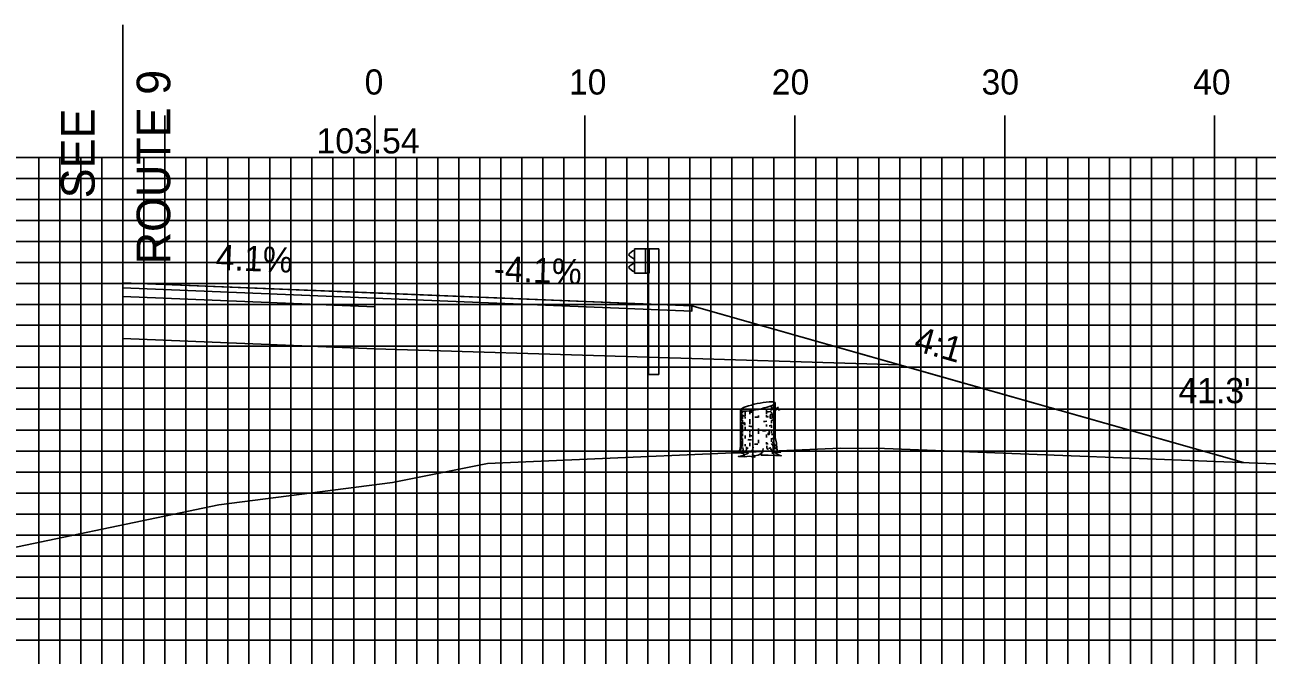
# Model space of a CAD drawing. Extents: x 852542 to 852886, y 364366 to 364586.
# Drawn here: x 852691.5 to 852750.7, y 364395.1 to 364425.1 of the extents above; entities that cross this region are included whole.
import ezdxf

# ---------------------------------------------------------------- set-up
doc = ezdxf.new("R2010")
doc.units = 0
for name, color, linetype in [('ANNOTATION', 7, 'Continuous'), ('D_Guardrail_Beam_Rt', 7, 'Continuous'), ('D_Roadway_Centerline_Text', 7, 'Continuous'), ('D_Roadway_Edge_Shoulder', 7, 'Continuous'), ('D_Roadway_Edge_TW', 7, 'Continuous'), ('D_Roadway_Pavement', 7, 'Continuous'), ('D_Roadway_SlopeLines', 7, 'Continuous'), ('D_Roadway_SubGrade', 7, 'Continuous'), ('D_Text_Standard', 7, 'Continuous'), ('H_V ANNOTATION', 7, 'Continuous'), ('M_Trees_Conifer_Pay', 7, 'Continuous'), ('MAJOR', 7, 'Continuous'), ('MINOR', 7, 'Continuous'), ('S_Roadway_Centerline', 7, 'Continuous')]:
    doc.layers.add(name, color=color, linetype=linetype)

msp = doc.modelspace()

# ---------------------------------------------------------------- linework, layer by layer
at = {"layer": 'D_Guardrail_Beam_Rt'}
for p, q in [((852720.466, 364414.331), (852720.322, 364414.231)), ((852720.322, 364414.088), (852720.518, 364413.952)), ((852720.556, 364414.352), (852720.482, 364414.338)), ((852720.556, 364414.436), (852721.243, 364414.436)), ((852720.556, 364413.269), (852720.556, 364414.436)), ((852721.077, 364414.436), (852721.077, 364413.269)), ((852721.181, 364414.436), (852721.181, 364413.269)), ((852721.243, 364414.436), (852721.714, 364414.436)), ((852721.243, 364414.436), (852721.243, 364413.269)), ((852721.714, 364414.436), (852721.714, 364408.436)), ((852720.518, 364413.753), (852720.322, 364413.617)), ((852720.322, 364413.474), (852720.466, 364413.374)), ((852720.551, 364413.888), (852720.551, 364413.817)), ((852720.482, 364413.367), (852720.556, 364413.352)), ((852721.243, 364413.269), (852720.556, 364413.269)), ((852721.222, 364408.436), (852721.222, 364413.269)), ((852721.222, 364408.436), (852721.714, 364408.436))]:
    msp.add_line(p, q, dxfattribs=at)
for centre, major_axis, start_param, end_param in [((852720.373, 364414.16), (-0.0877, 0), 5.323254, 7.243116), ((852720.49, 364414.297), (-0.0417, 0), 4.907132, 5.323254), ((852720.373, 364413.545), (-0.0877, 0), 5.323254, 7.243116), ((852720.472, 364413.888), (0.0789, 0), 0, 0.959931), ((852720.472, 364413.817), (0.0789, 0), 5.323254, 6.283185), ((852720.49, 364413.408), (-0.0417, 0), 0.959931, 1.376053)]:
    msp.add_ellipse(centre, major_axis=major_axis, ratio=0.995501, start_param=start_param, end_param=end_param, dxfattribs=at)
at = {"layer": 'D_Roadway_Edge_Shoulder'}
for points in [[(852696.178, 364412.82), (852723.285, 364411.714), (852723.285, 364411.464), (852696.178, 364412.57)], [(852696.178, 364412.82), (852723.285, 364411.714), (852723.285, 364411.464), (852696.178, 364412.57)], [(852696.178, 364412.82), (852723.285, 364411.714), (852723.285, 364411.464), (852696.178, 364412.57)], [(852696.178, 364412.82), (852723.285, 364411.714), (852723.285, 364411.464), (852696.178, 364412.57)], [(852696.178, 364412.82), (852723.285, 364411.714), (852723.285, 364411.464), (852696.178, 364412.57)], [(852708.178, 364412.331), (852723.285, 364411.714), (852723.285, 364411.464), (852708.178, 364412.081)], [(852708.178, 364412.331), (852723.285, 364411.714), (852723.285, 364411.464), (852708.178, 364412.081)], [(852708.178, 364412.331), (852723.285, 364411.714), (852723.285, 364411.464), (852708.178, 364412.081)]]:
    msp.add_lwpolyline(points, close=True, dxfattribs=at)
at = {"layer": 'D_Roadway_Edge_TW'}
msp.add_lwpolyline([(852696.178, 364412.82), (852696.178, 364412.57)], dxfattribs=at)
msp.add_lwpolyline([(852696.178, 364412.82), (852696.178, 364412.57)], dxfattribs=at)
msp.add_lwpolyline([(852696.178, 364412.82), (852708.178, 364412.331), (852708.178, 364412.081), (852696.178, 364412.57)], close=True, dxfattribs=at)
msp.add_lwpolyline([(852696.178, 364412.82), (852708.178, 364412.331), (852708.178, 364412.081), (852696.178, 364412.57)], close=True, dxfattribs=at)
msp.add_lwpolyline([(852696.178, 364412.82), (852708.178, 364412.331), (852708.178, 364412.081), (852696.178, 364412.57)], close=True, dxfattribs=at)
at = {"layer": 'D_Roadway_Pavement'}
for points in [[(852696.178, 364412.57), (852696.178, 364412.154)], [(852696.178, 364412.57), (852696.178, 364412.154)], [(852696.178, 364412.57), (852696.178, 364412.154)], [(852696.178, 364412.57), (852696.178, 364412.154)], [(852708.178, 364412.081), (852708.178, 364411.664)], [(852708.178, 364412.081), (852708.178, 364411.664)], [(852708.178, 364412.081), (852708.178, 364411.664)], [(852708.178, 364412.081), (852708.178, 364411.664)], [(852708.178, 364412.081), (852708.178, 364411.664)], [(852708.178, 364412.081), (852708.178, 364411.664)], [(852708.178, 364412.081), (852708.178, 364411.664)], [(852708.178, 364412.081), (852708.178, 364411.664)], [(852708.178, 364412.081), (852708.178, 364411.664)], [(852708.178, 364412.081), (852708.178, 364411.664)], [(852708.178, 364412.081), (852708.178, 364411.664)], [(852708.178, 364412.081), (852708.178, 364411.664)], [(852708.178, 364412.081), (852708.178, 364411.664)], [(852708.178, 364412.081), (852708.178, 364411.664)]]:
    msp.add_lwpolyline(points, dxfattribs=at)
msp.add_lwpolyline([(852696.178, 364412.57), (852708.178, 364412.081), (852708.178, 364411.664), (852696.178, 364412.154)], close=True, dxfattribs=at)
msp.add_lwpolyline([(852696.178, 364412.57), (852708.178, 364412.081), (852708.178, 364411.664), (852696.178, 364412.154)], close=True, dxfattribs=at)
msp.add_lwpolyline([(852696.178, 364412.57), (852708.178, 364412.081), (852708.178, 364411.664), (852696.178, 364412.154)], close=True, dxfattribs=at)
at = {"layer": 'D_Roadway_SlopeLines'}
for points in [[(852723.285, 364411.714), (852735.285, 364408.301), (852749.548, 364404.244)], [(852723.285, 364411.714), (852735.285, 364408.301), (852749.548, 364404.244)], [(852723.285, 364411.714), (852735.285, 364408.301), (852749.548, 364404.244)], [(852723.285, 364411.714), (852735.285, 364408.301), (852749.548, 364404.244)], [(852723.285, 364411.714), (852749.548, 364404.244)]]:
    msp.add_lwpolyline(points, dxfattribs=at)
at = {"layer": 'D_Roadway_SubGrade'}
msp.add_line((852696.178, 364425.111), (852696.178, 364410.154), dxfattribs=at)
for points in [[(852696.178, 364412.154), (852708.178, 364411.664), (852708.178, 364409.664), (852696.178, 364410.154)], [(852696.178, 364412.154), (852708.178, 364411.664), (852708.178, 364409.664), (852696.178, 364410.154)], [(852696.178, 364412.154), (852708.178, 364411.664), (852708.178, 364409.664), (852696.178, 364410.154)], [(852708.178, 364411.664), (852708.178, 364412.081), (852723.285, 364411.464), (852723.285, 364411.714), (852733.164, 364408.905), (852708.178, 364409.664)], [(852708.178, 364411.664), (852708.178, 364412.081), (852723.285, 364411.464), (852723.285, 364411.714), (852733.164, 364408.905), (852708.178, 364409.664)], [(852708.178, 364411.664), (852708.178, 364412.081), (852723.285, 364411.464), (852723.285, 364411.714), (852733.164, 364408.905), (852708.178, 364409.664)], [(852708.178, 364411.664), (852708.178, 364412.081), (852723.285, 364411.464), (852723.285, 364411.714), (852733.164, 364408.905), (852708.178, 364409.664)]]:
    msp.add_lwpolyline(points, close=True, dxfattribs=at)
msp.add_lwpolyline([(852696.178, 364412.154), (852696.178, 364410.154)], dxfattribs=at)
msp.add_lwpolyline([(852696.178, 364412.154), (852696.178, 364410.154)], dxfattribs=at)
at = {"layer": 'M_Trees_Conifer_Pay'}
for p, q in [((852727.065, 364406.952), (852727.065, 364406.729)), ((852727.182, 364407.013), (852727.182, 364406.85)), ((852727.254, 364405.438), (852727.254, 364407.085)), ((852725.589, 364405.028), (852725.589, 364406.75)), ((852725.637, 364406.713), (852725.637, 364406.242)), ((852725.695, 364406.701), (852725.695, 364406.604)), ((852725.695, 364406.53), (852725.695, 364406.325)), ((852725.82, 364406.694), (852725.82, 364406.461)), ((852725.82, 364406.421), (852725.82, 364406.346)), ((852726.04, 364406.714), (852726.04, 364406.546)), ((852726.04, 364406.309), (852726.04, 364406.072)), ((852726.446, 364406.482), (852726.446, 364406.387)), ((852726.836, 364406.756), (852726.836, 364406.556)), ((852726.836, 364406.499), (852726.836, 364406.41)), ((852727.065, 364406.64), (852727.065, 364406.593)), ((852727.122, 364406.457), (852727.07, 364406.398)), ((852727.182, 364406.783), (852727.182, 364406.655)), ((852727.182, 364406.468), (852727.182, 364406.132)), ((852725.637, 364406.177), (852725.637, 364405.869)), ((852725.637, 364405.822), (852725.637, 364405.329)), ((852725.695, 364406.268), (852725.695, 364406.068)), ((852725.695, 364406.021), (852725.695, 364405.685)), ((852725.82, 364405.943), (852725.82, 364405.805)), ((852726.04, 364405.827), (852726.04, 364405.675)), ((852726.446, 364405.869), (852726.446, 364405.795)), ((852726.446, 364405.77), (852726.446, 364405.621)), ((852726.836, 364406.062), (852726.836, 364405.957)), ((852727.065, 364406.258), (852727.065, 364406.126)), ((852727.065, 364406.015), (852727.065, 364405.906)), ((852727.065, 364405.77), (852727.065, 364405.628)), ((852727.182, 364406.095), (852727.182, 364405.932)), ((852727.182, 364405.885), (852727.182, 364405.669)), ((852725.637, 364405.276), (852725.637, 364405.028)), ((852725.695, 364405.632), (852725.695, 364405.496)), ((852725.695, 364405.397), (852725.695, 364405.018)), ((852725.82, 364405.533), (852725.82, 364405.391)), ((852725.82, 364405.129), (852725.82, 364405.035)), ((852726.04, 364405.632), (852726.04, 364405.459)), ((852726.04, 364405.181), (852726.04, 364405.028)), ((852726.446, 364405.329), (852726.446, 364405.177)), ((852726.836, 364405.591), (852726.836, 364405.444)), ((852726.836, 364405.212), (852726.836, 364405.123)), ((852727.065, 364405.401), (852727.065, 364405.228)), ((852727.182, 364405.638), (852727.182, 364405.564)), ((852727.182, 364405.523), (852727.182, 364405.35)), ((852725.82, 364404.635), (852725.983, 364404.699)), ((852726.257, 364404.571), (852726.131, 364404.635))]:
    msp.add_line(p, q, dxfattribs=at)
for points in [[(852727.07, 364406.583), (852727.107, 364406.509), (852727.154, 364406.566), (852727.212, 364406.635), (852727.305, 364406.828), (852727.369, 364406.875), (852727.4, 364406.882)], [(852727.037, 364406.546), (852727.006, 364406.461), (852727.002, 364406.394), (852727.033, 364406.33)], [(852727.085, 364406.33), (852727.122, 364406.457), (852727.185, 364406.573), (852727.216, 364406.64), (852727.285, 364406.787)], [(852727.299, 364406.816), (852727.375, 364406.824), (852727.447, 364406.725)], [(852725.769, 364406.056), (852725.763, 364406.151), (852725.806, 364406.128), (852725.806, 364406.034)], [(852726.908, 364405.657), (852726.92, 364405.58), (852726.967, 364405.591), (852726.955, 364405.757)], [(852727.254, 364405.438), (852727.305, 364405.177), (852727.321, 364404.903), (852727.379, 364404.778), (852727.515, 364404.747), (852727.284, 364404.709), (852727.284, 364404.709), (852727.29, 364404.662), (852727.538, 364404.568), (852727.263, 364404.584), (852726.908, 364404.604), (852726.586, 364404.594), (852726.593, 364404.677), (852726.444, 364404.594), (852726.257, 364404.571), (852726.282, 364404.503), (852726.014, 364404.547), (852725.794, 364404.52), (852725.501, 364404.537), (852725.79, 364404.594), (852725.82, 364404.635), (852725.658, 364404.693), (852725.421, 364404.703), (852725.18, 364404.703), (852725.522, 364404.761), (852725.563, 364404.841), (852725.589, 364405.028)], [(852727.08, 364405.15), (852727.154, 364405.045), (852727.159, 364404.872), (852727.284, 364404.709)], [(852727.179, 364405.296), (852727.185, 364405.15), (852727.233, 364405.082), (852727.243, 364404.883)], [(852725.637, 364404.981), (852725.616, 364404.903), (852725.596, 364404.808)], [(852725.715, 364404.961), (852725.721, 364404.845), (852725.668, 364404.757), (852725.658, 364404.693)], [(852725.878, 364404.988), (852725.878, 364404.856), (852725.79, 364404.757)], [(852726.105, 364404.747), (852726.172, 364404.841), (852726.199, 364404.981)], [(852726.593, 364404.677), (852726.667, 364404.818), (852726.677, 364404.919)], [(852726.843, 364405.045), (852726.854, 364404.919), (852726.928, 364404.876)], [(852727.122, 364404.656), (852727.107, 364404.794), (852727.033, 364404.923)]]:
    msp.add_lwpolyline(points, dxfattribs=at)
for centre, radius, start, end in [((852726.088, 364406.144), 0.802, 108.05939, 124.2194), ((852727.445, 364401.983), 5.179, 101.7194, 108.05939), ((852727.445, 364401.983), 5.179, 95.37941, 101.7194), ((852725.398, 364411.853), 5.179, 281.7194, 288.05939), ((852727.035, 364406.34), 0.802, 79.2194, 95.37941), ((852726.755, 364407.691), 0.802, 288.05939, 304.2194), ((852727.138, 364406.882), 0.251, 71.05013, 79.2194), ((852727.065, 364407.236), 0.251, 304.2194, 312.38868), ((852727.122, 364407.054), 0.172, 300, 311.25059), ((852727.193, 364407.041), 0.0817, 56.7194, 71.05013), ((852727.179, 364407.111), 0.0817, 312.38868, 326.7194), ((852727.194, 364406.971), 0.0624, 311.25059, 330), ((852727.209, 364407.066), 0.0527, 46.92298, 56.7194), ((852727.223, 364407.081), 0.0314, 34.2194, 46.92298), ((852727.203, 364407.095), 0.0527, 326.7194, 336.51582), ((852727.21, 364406.962), 0.0441, 330, 343.94846), ((852727.227, 364407.084), 0.0264, 23.40735, 34.2194), ((852727.222, 364407.086), 0.0314, 336.51582, 349.2194), ((852727.231, 364407.086), 0.0226, 11.7194, 23.40735), ((852727.22, 364406.959), 0.0334, 343.94846, 354.21506), ((852727.231, 364407.086), 0.0226, 0.03145, 11.7194), ((852727.227, 364407.086), 0.0264, 349.2194, 0.03145), ((852725.622, 364406.572), 0.0334, 163.94846, 180), ((852725.622, 364406.572), 0.0334, 180, 196.05154), ((852725.621, 364406.749), 0.0314, 156.51582, 169.2194), ((852725.616, 364406.75), 0.0264, 169.2194, 180.03145), ((852725.612, 364406.75), 0.0226, 180.03145, 191.7194), ((852725.612, 364406.75), 0.0226, 191.7194, 203.40735), ((852725.632, 364406.575), 0.0441, 196.05154, 210), ((852725.616, 364406.751), 0.0264, 203.40735, 214.2194), ((852725.64, 364406.74), 0.0527, 146.7194, 156.51582), ((852725.62, 364406.754), 0.0314, 214.2194, 226.92298), ((852725.648, 364406.584), 0.0624, 210, 228.74941), ((852725.665, 364406.724), 0.0817, 132.38868, 146.7194), ((852725.634, 364406.77), 0.0527, 226.92298, 236.7194), ((852725.65, 364406.794), 0.0817, 236.7194, 251.05013), ((852725.72, 364406.666), 0.172, 228.74941, 240), ((852725.779, 364406.6), 0.251, 124.2194, 132.38868), ((852725.705, 364406.954), 0.251, 251.05013, 259.2194), ((852725.919, 364407.012), 0.571, 240, 240.33672), ((852725.921, 364406.8), 0.571, 240, 247.05866), ((852725.808, 364407.495), 0.802, 259.2194, 275.37941), ((852725.919, 364407.012), 0.571, 246.85973, 257.98457), ((852725.398, 364411.853), 5.179, 275.37941, 281.7194), ((852726.422, 364410.762), 4.124, 264.6955, 266.73309), ((852726.42, 364410.529), 4.124, 268.07512, 270), ((852726.42, 364410.529), 4.124, 270, 270.35814), ((852726.42, 364410.529), 4.124, 275.78493, 277.05584), ((852726.422, 364410.762), 4.124, 276.23804, 278.1032), ((852726.923, 364407.244), 0.571, 278.1032, 284.36665), ((852726.923, 364407.399), 0.571, 284.43166, 292.41325), ((852726.922, 364406.8), 0.571, 284.44928, 297.04285), ((852726.923, 364407.244), 0.571, 297.0237, 300), ((852727.122, 364406.899), 0.172, 300, 311.25059), ((852727.194, 364406.817), 0.0624, 311.25059, 330), ((852727.21, 364406.808), 0.0441, 330, 343.94846), ((852727.22, 364406.805), 0.0334, 343.94846, 354.21506), ((852727.22, 364406.361), 0.0334, 343.94846, 354.21506), ((852725.622, 364406.125), 0.0334, 163.94846, 180), ((852725.622, 364406.125), 0.0334, 180, 196.05154), ((852725.622, 364405.915), 0.0334, 163.94846, 180), ((852725.622, 364405.915), 0.0334, 180, 196.05154), ((852725.632, 364406.128), 0.0441, 196.05154, 210), ((852725.632, 364405.918), 0.0441, 196.05154, 210), ((852725.648, 364406.137), 0.0624, 210, 228.74941), ((852725.648, 364405.927), 0.0624, 210, 228.74941), ((852725.72, 364406.22), 0.172, 228.74941, 240), ((852725.72, 364406.01), 0.172, 228.74941, 240), ((852725.919, 364406.565), 0.571, 240, 240.33672), ((852725.919, 364406.355), 0.571, 240, 246.85973), ((852725.919, 364406.355), 0.571, 259.27072, 261.8968), ((852726.42, 364409.872), 4.124, 261.8968, 263.14738), ((852726.42, 364410.082), 4.124, 264.08098, 266.66759), ((852726.42, 364409.872), 4.124, 270, 270.35814), ((852726.42, 364409.872), 4.124, 273.14934, 275.45691), ((852726.422, 364410.318), 4.124, 273.70524, 275.95043), ((852726.42, 364410.082), 4.124, 277.61247, 278.1032), ((852726.921, 364406.565), 0.571, 278.1032, 286.92962), ((852726.921, 364406.565), 0.571, 297.18959, 300), ((852726.921, 364406.355), 0.571, 297.18959, 300), ((852727.12, 364406.22), 0.172, 300, 311.25059), ((852727.12, 364406.01), 0.172, 300, 311.25059), ((852727.193, 364406.137), 0.0624, 311.25059, 330), ((852727.193, 364405.927), 0.0624, 311.25059, 330), ((852727.209, 364406.128), 0.0441, 330, 343.94846), ((852727.209, 364405.918), 0.0441, 330, 343.94846), ((852727.219, 364406.125), 0.0334, 343.94846, 354.21506), ((852727.219, 364405.915), 0.0334, 343.94846, 354.21506), ((852725.622, 364405.678), 0.0334, 163.94846, 180), ((852725.622, 364405.678), 0.0334, 180, 196.05154), ((852725.622, 364405.481), 0.0334, 163.94846, 180), ((852725.622, 364405.285), 0.0334, 163.94846, 180), ((852725.622, 364405.285), 0.0334, 180, 196.05154), ((852725.632, 364405.681), 0.0441, 196.05154, 210), ((852725.632, 364405.288), 0.0441, 196.05154, 210), ((852725.648, 364405.69), 0.0624, 210, 228.74941), ((852725.648, 364405.297), 0.0624, 210, 228.74941), ((852725.72, 364405.773), 0.172, 228.74941, 240), ((852725.72, 364405.38), 0.172, 228.74941, 240), ((852725.919, 364406.118), 0.571, 240, 246.85973), ((852725.909, 364405.926), 0.571, 241.23686, 248.02677), ((852725.919, 364405.725), 0.571, 240, 246.85973), ((852726.42, 364409.438), 4.124, 263.49906, 265.83975), ((852726.42, 364409.636), 4.124, 264.71603, 266.31934), ((852726.42, 364409.242), 4.124, 267.81166, 270), ((852726.42, 364409.242), 4.124, 270, 270.13279), ((852726.42, 364409.242), 4.124, 275.78493, 276.78961), ((852726.921, 364406.118), 0.571, 285.39827, 297.18959), ((852726.921, 364405.725), 0.571, 288.50673, 297.27208), ((852726.921, 364405.92), 0.571, 289.29072, 300), ((852727.12, 364405.575), 0.172, 300, 311.25059), ((852727.193, 364405.493), 0.0624, 311.25059, 330), ((852727.209, 364405.483), 0.0441, 330, 343.94846), ((852727.219, 364405.481), 0.0334, 343.94846, 354.21506), ((852725.622, 364405.065), 0.0334, 163.94846, 180), ((852725.622, 364405.065), 0.0334, 180, 196.05154), ((852725.632, 364405.068), 0.0441, 196.05154, 210), ((852725.648, 364405.077), 0.0624, 210, 228.74941), ((852725.72, 364405.159), 0.172, 228.74941, 240), ((852725.919, 364405.504), 0.571, 240, 244.53138), ((852726.42, 364409.022), 4.124, 262.44379, 263.51202), ((852726.42, 364409.022), 4.124, 277.36842, 278.1032), ((852726.921, 364405.504), 0.571, 278.1032, 281.63703), ((852727.12, 364405.159), 0.172, 300, 311.25059), ((852727.193, 364405.077), 0.0624, 311.25059, 330), ((852727.209, 364405.068), 0.0441, 330, 343.94846), ((852727.219, 364405.065), 0.0334, 343.94846, 354.21506)]:
    msp.add_arc(centre, radius, start, end, dxfattribs=at)
at = {"layer": 'MAJOR'}
for p, q in [((852698.178, 364420.791), (852698.178, 364418.787)), ((852708.178, 364420.791), (852708.178, 364418.787)), ((852718.178, 364420.791), (852718.178, 364418.787)), ((852728.178, 364420.791), (852728.178, 364418.787)), ((852738.178, 364420.791), (852738.178, 364418.787)), ((852748.178, 364420.791), (852748.178, 364418.787)), ((852568.178, 364418.787), (852848.178, 364418.787)), ((852568.178, 364418.787), (852848.178, 364418.787)), ((852698.178, 364383.787), (852698.178, 364418.787)), ((852708.178, 364383.787), (852708.178, 364418.787)), ((852718.178, 364383.787), (852718.178, 364418.787)), ((852728.178, 364383.787), (852728.178, 364418.787)), ((852738.178, 364383.787), (852738.178, 364418.787)), ((852748.178, 364383.787), (852748.178, 364418.787)), ((852568.178, 364413.787), (852848.178, 364413.787)), ((852568.178, 364408.787), (852848.178, 364408.787)), ((852568.178, 364403.787), (852848.178, 364403.787)), ((852568.178, 364398.787), (852848.178, 364398.787))]:
    msp.add_line(p, q, dxfattribs=at)
at = {"layer": 'MINOR'}
for p, q in [((852692.178, 364383.787), (852692.178, 364418.787)), ((852693.178, 364383.787), (852693.178, 364418.787)), ((852694.178, 364383.787), (852694.178, 364418.787)), ((852695.178, 364383.787), (852695.178, 364418.787)), ((852696.178, 364383.787), (852696.178, 364418.787)), ((852697.178, 364383.787), (852697.178, 364418.787)), ((852699.178, 364383.787), (852699.178, 364418.787)), ((852700.178, 364383.787), (852700.178, 364418.787)), ((852701.178, 364383.787), (852701.178, 364418.787)), ((852702.178, 364383.787), (852702.178, 364418.787)), ((852703.178, 364383.787), (852703.178, 364418.787)), ((852704.178, 364383.787), (852704.178, 364418.787)), ((852705.178, 364383.787), (852705.178, 364418.787)), ((852706.178, 364383.787), (852706.178, 364418.787)), ((852707.178, 364383.787), (852707.178, 364418.787)), ((852709.178, 364383.787), (852709.178, 364418.787)), ((852710.178, 364383.787), (852710.178, 364418.787)), ((852711.178, 364383.787), (852711.178, 364418.787)), ((852712.178, 364383.787), (852712.178, 364418.787)), ((852713.178, 364383.787), (852713.178, 364418.787)), ((852714.178, 364383.787), (852714.178, 364418.787)), ((852715.178, 364383.787), (852715.178, 364418.787)), ((852716.178, 364383.787), (852716.178, 364418.787)), ((852717.178, 364383.787), (852717.178, 364418.787)), ((852719.178, 364383.787), (852719.178, 364418.787)), ((852720.178, 364383.787), (852720.178, 364418.787)), ((852721.178, 364383.787), (852721.178, 364418.787)), ((852722.178, 364383.787), (852722.178, 364418.787)), ((852723.178, 364383.787), (852723.178, 364418.787)), ((852724.178, 364383.787), (852724.178, 364418.787)), ((852725.178, 364383.787), (852725.178, 364418.787)), ((852726.178, 364383.787), (852726.178, 364418.787)), ((852727.178, 364383.787), (852727.178, 364418.787)), ((852729.178, 364383.787), (852729.178, 364418.787)), ((852730.178, 364383.787), (852730.178, 364418.787)), ((852731.178, 364383.787), (852731.178, 364418.787)), ((852732.178, 364383.787), (852732.178, 364418.787)), ((852733.178, 364383.787), (852733.178, 364418.787)), ((852734.178, 364383.787), (852734.178, 364418.787)), ((852735.178, 364383.787), (852735.178, 364418.787)), ((852736.178, 364383.787), (852736.178, 364418.787)), ((852737.178, 364383.787), (852737.178, 364418.787)), ((852739.178, 364383.787), (852739.178, 364418.787)), ((852740.178, 364383.787), (852740.178, 364418.787)), ((852741.178, 364383.787), (852741.178, 364418.787)), ((852742.178, 364383.787), (852742.178, 364418.787)), ((852743.178, 364383.787), (852743.178, 364418.787)), ((852744.178, 364383.787), (852744.178, 364418.787)), ((852745.178, 364383.787), (852745.178, 364418.787)), ((852746.178, 364383.787), (852746.178, 364418.787)), ((852747.178, 364383.787), (852747.178, 364418.787)), ((852749.178, 364383.787), (852749.178, 364418.787)), ((852750.178, 364383.787), (852750.178, 364418.787)), ((852568.178, 364417.787), (852848.178, 364417.787)), ((852568.178, 364416.787), (852848.178, 364416.787)), ((852568.178, 364415.787), (852848.178, 364415.787)), ((852568.178, 364414.787), (852848.178, 364414.787)), ((852568.178, 364412.787), (852848.178, 364412.787)), ((852568.178, 364411.787), (852848.178, 364411.787)), ((852568.178, 364410.787), (852848.178, 364410.787)), ((852568.178, 364409.787), (852848.178, 364409.787)), ((852568.178, 364407.787), (852848.178, 364407.787)), ((852568.178, 364406.787), (852848.178, 364406.787)), ((852568.178, 364405.787), (852848.178, 364405.787)), ((852568.178, 364404.787), (852848.178, 364404.787)), ((852568.178, 364402.787), (852848.178, 364402.787)), ((852568.178, 364401.787), (852848.178, 364401.787)), ((852568.178, 364400.787), (852848.178, 364400.787)), ((852568.178, 364399.787), (852848.178, 364399.787)), ((852568.178, 364397.787), (852848.178, 364397.787)), ((852568.178, 364396.787), (852848.178, 364396.787)), ((852568.178, 364395.787), (852848.178, 364395.787))]:
    msp.add_line(p, q, dxfattribs=at)
at = {"layer": 'S_Roadway_Centerline'}
msp.add_lwpolyline([(852688.559, 364399.681), (852700.745, 364402.23), (852709.021, 364403.295), (852713.555, 364404.197), (852730.362, 364404.925), (852731.345, 364404.917), (852732.055, 364404.933), (852753.053, 364404.106), (852763.798, 364404.097), (852768.436, 364403.632), (852771.519, 364403.34), (852784.623, 364400.763), (852790.954, 364399.495), (852792.561, 364399.185), (852795.206, 364398.758), (852804.722, 364397.391), (852810.397, 364396.754), (852825.7, 364395.636), (852828.854, 364395.467), (852839.509, 364395.389), (852847.407, 364395.342), (852848.178, 364395.458)], dxfattribs=at)

# ---------------------------------------------------------------- texts
at = {"layer": 'ANNOTATION'}
for s, height, rotation, p in [('ROUTE 9', 1.6, 90, (852698.439, 364413.69)), ('SEE', 1.6, 90, (852694.839, 364416.84)), ('4.1%', 1.2, 357.66362, (852700.592, 364413.442)), ('-4.1%', 1.2, 357.66368, (852713.825, 364412.902)), ('4:1', 1.2, 344.12189, (852733.801, 364409.603))]:
    msp.add_text(s, height=height, rotation=rotation, dxfattribs=at).set_placement(p)
at = {"layer": 'D_Roadway_Centerline_Text'}
msp.add_text('103.54', height=1.2, dxfattribs=at).set_placement((852705.406, 364418.981))
at = {"layer": 'D_Text_Standard'}
msp.add_text("41.3'", height=1.2, dxfattribs=at).set_placement((852746.455, 364407.076))
at = {"layer": 'H_V ANNOTATION'}
for s, p in [('0', (852707.696, 364421.787)), ('10', (852717.429, 364421.787)), ('20', (852727.086, 364421.787)), ('30', (852737.076, 364421.787)), ('40', (852747.151, 364421.787))]:
    msp.add_text(s, height=1.2, dxfattribs=at).set_placement(p)

doc.saveas('drawing.dxf')
